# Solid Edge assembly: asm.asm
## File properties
Author: Deepak Maini
Template: Normal.asm
Last saved by: CADCIM
Revision: 9
Application: Solid Edge
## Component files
endplatemod.par
diskmod.par
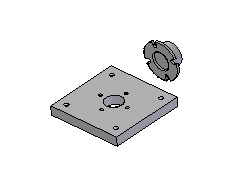
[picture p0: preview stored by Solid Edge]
